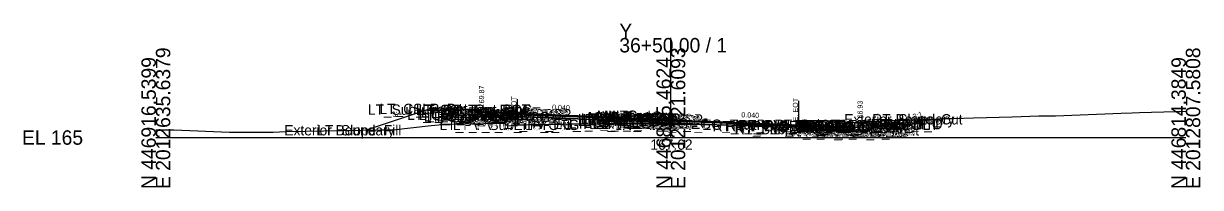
# Model space of a CAD drawing. Extents: x -26 to 3203, y -10 to 9532.
# Drawn here: x 2974.3 to 3202.8, y 490.3 to 522.1 of the extents above; entities that cross this region are included whole.
import ezdxf

# ---------------------------------------------------------------- set-up
doc = ezdxf.new("R2010")
doc.units = 0
for name, color, linetype in [('Default', 7, 'Continuous'), ('Exist CMT Pavement', 7, 'Continuous'), ('Exist Cross Section Cell', 7, 'Continuous'), ('Exist XS Center Line Elevation Label', 7, 'Continuous'), ('Exist XS Ground Line', 7, 'Continuous'), ('Prop CMT Conc Surface', 7, 'Continuous'), ('Prop CMT Concrete Structures', 7, 'Continuous'), ('Prop CMT Pvmt Course 1', 7, 'Continuous'), ('Prop CMT Pvmt Course 1 CG', 7, 'Continuous'), ('Prop CMT Pvmt Course 1 Wedge', 7, 'Continuous'), ('Prop CMT Pvmt Course 2', 7, 'Continuous'), ('Prop CMT Pvmt Course 2 Wedge', 7, 'Continuous'), ('Prop CMT Pvmt Course 3', 7, 'Continuous'), ('Prop CMT Pvmt Course 3 Wedge', 7, 'Continuous'), ('Prop CMT Pvmt Surface', 7, 'Continuous'), ('Prop CMT Pvmt Wedge Surface 1', 7, 'Continuous'), ('Prop CMT Pvmt Wedge Surface 2', 7, 'Continuous'), ('Prop CMT Pvmt Wedge Surface 3', 7, 'Continuous'), ('Prop CMT Slope Grass', 7, 'Continuous'), ('Prop CMT Subgrade Earthwork', 7, 'Continuous'), ('Prop XS Hydro Elevations', 7, 'Continuous'), ('Prop XS Label Text', 7, 'Continuous'), ('Prop XS SE Text', 7, 'Continuous'), ('Prop XS Side Slope Text', 7, 'Continuous'), ('Scratch_Level_0', 7, 'Continuous')]:
    doc.layers.add(name, color=color, linetype=linetype)

msp = doc.modelspace()

# ---------------------------------------------------------------- linework, layer by layer
at = {"layer": 'Exist CMT Pavement'}
msp.add_lwpolyline([(3070.13, 502.45), (3070.68, 502.46), (3071.43, 502.47), (3073.24, 502.5), (3074.4, 502.53), (3074.77, 502.53), (3076.32, 502.56), (3076.88, 502.57), (3077.22, 502.57), (3078.71, 502.6), (3080.14, 502.63), (3081.2, 502.64), (3083.01, 502.66), (3085, 502.68), (3085.38, 502.68), (3086.08, 502.69), (3088.82, 502.72), (3089.84, 502.72), (3091.31, 502.73), (3091.74, 502.73), (3093.28, 502.72), (3094.64, 502.7), (3095.09, 502.7), (3095.86, 502.68), (3096.94, 502.67), (3097.58, 502.66), (3100.05, 502.62), (3100.77, 502.6), (3101.8, 502.59), (3103.4, 502.56), (3105.7, 502.53), (3106.31, 502.53), (3107.91, 502.5), (3109.21, 502.49), (3110.03, 502.48), (3111.1, 502.47), (3111.53, 502.47), (3112.11, 502.47), (3113.36, 502.46), (3115, 502.45), (3115.47, 502.44), (3116.99, 502.43), (3117.9, 502.42), (3118.81, 502.41), (3120.34, 502.4), (3121.06, 502.37), (3123.23, 502.22), (3123.69, 502.18), (3124.79, 502.12)], dxfattribs=at)
at = {"layer": 'Exist Cross Section Cell'}
for p, q in [((3100, 500), (3100, 519.32)), ((3000, 500), (3100, 500)), ((3100, 500), (3200, 500))]:
    msp.add_line(p, q, dxfattribs=at)
at = {"layer": 'Exist XS Ground Line'}
msp.add_lwpolyline([(3000, 501.52), (3000.37, 501.52), (3003.48, 501.48), (3014.31, 501.01), (3022.78, 501.07), (3025.26, 501.14), (3043.64, 501.46), (3046.03, 501.52), (3053.47, 502.34), (3056.38, 502.58), (3063.7, 502.71), (3067.62, 502.76), (3068.42, 502.3), (3070.13, 502.45), (3070.68, 502.46), (3071.43, 502.47), (3073.24, 502.5), (3074.4, 502.53), (3074.77, 502.53), (3076.32, 502.56), (3076.88, 502.57), (3077.22, 502.57), (3078.71, 502.6), (3080.14, 502.63), (3081.2, 502.64), (3083.01, 502.66), (3085, 502.68), (3085.38, 502.68), (3086.08, 502.69), (3088.82, 502.72), (3089.84, 502.72), (3091.31, 502.73), (3091.74, 502.73), (3093.28, 502.72), (3094.64, 502.7), (3095.09, 502.7), (3095.86, 502.68), (3096.94, 502.67), (3097.58, 502.66), (3100.05, 502.62), (3100.77, 502.6), (3101.8, 502.59), (3103.4, 502.56), (3105.7, 502.53), (3106.31, 502.53), (3107.91, 502.5), (3109.21, 502.49), (3110.03, 502.48), (3111.1, 502.47), (3111.53, 502.47), (3112.11, 502.47), (3113.36, 502.46), (3115, 502.45), (3115.47, 502.44), (3116.99, 502.43), (3117.9, 502.42), (3118.81, 502.41), (3120.34, 502.4), (3121.06, 502.37), (3123.23, 502.22), (3123.69, 502.18), (3124.79, 502.12), (3125.27, 502.1), (3125.91, 502.08), (3126.45, 502.32), (3126.79, 502.5), (3127.11, 502.68), (3127.46, 502.77), (3128.1, 502.84), (3129.65, 503.06), (3130.84, 503.2), (3131.19, 503.21), (3133.13, 503.39), (3133.59, 503.09), (3133.9, 502.88), (3134.08, 502.83), (3135.32, 502.91), (3136.4, 503.07), (3137.39, 503.08), (3150.31, 503.57), (3152.8, 503.66), (3154.94, 503.72), (3158.75, 503.83), (3166.29, 504.04), (3171.44, 504.18), (3174.71, 504.24), (3187.42, 504.7), (3189.56, 504.78), (3191.02, 504.84), (3198.06, 505.05), (3198.92, 505.07), (3200, 505.12)], dxfattribs=at)
at = {"layer": 'Prop CMT Conc Surface'}
for points in [[(3058.75, 505.46), (3053.75, 505.56)], [(3063.25, 504.87), (3063.25, 505.37), (3062.75, 505.37)], [(3065.25, 504.87), (3063.25, 504.87)], [(3134.75, 502.09), (3136.75, 501.93)], [(3136.75, 501.93), (3136.75, 502.43), (3137.25, 502.43)], [(3141.25, 502.52), (3146.25, 502.62)]]:
    msp.add_lwpolyline(points, dxfattribs=at)
at = {"layer": 'Prop CMT Concrete Structures'}
for points in [[(3053.75, 505.23), (3053.75, 505.56)], [(3053.75, 505.56), (3058.75, 505.46)], [(3058.75, 505.13), (3053.75, 505.23)], [(3058.75, 505.46), (3058.75, 505.13)], [(3065.25, 504.87), (3063.25, 504.87), (3063.25, 505.37), (3062.75, 505.37)], [(3062.75, 505.37), (3062.75, 504.39), (3065.25, 504.29)], [(3065.25, 504.29), (3065.25, 504.87)], [(3096, 503.64), (3095.99, 503.81), (3095.24, 504.06), (3094, 504.24), (3092.76, 504.22), (3092.01, 503.97), (3092, 503.8)], [(3092, 503.8), (3096, 503.64)], [(3134.75, 502.09), (3136.75, 501.93), (3136.75, 502.43), (3137.25, 502.43)], [(3137.25, 502.43), (3137.25, 501.41), (3134.75, 501.51)], [(3134.75, 501.51), (3134.75, 502.09)], [(3146.25, 502.62), (3141.25, 502.52)], [(3141.25, 502.52), (3141.25, 502.19)], [(3141.25, 502.19), (3146.25, 502.29)], [(3146.25, 502.29), (3146.25, 502.62)]]:
    msp.add_lwpolyline(points, dxfattribs=at)
at = {"layer": 'Prop CMT Pvmt Course 1'}
for points in [[(3092, 503.8), (3065.25, 504.87)], [(3065.25, 504.87), (3065.25, 504.62)], [(3065.25, 504.62), (3070.13, 504.43)], [(3070.13, 504.43), (3070.13, 504.55)], [(3074.77, 504.37), (3092, 503.68)], [(3092, 503.8), (3096, 503.64)], [(3092, 503.55), (3092, 503.8)], [(3092, 503.55), (3092, 503.8)], [(3092, 503.68), (3092, 503.55), (3092, 503.55)], [(3096, 503.39), (3092, 503.55)], [(3096, 503.64), (3096, 503.39)], [(3096, 503.64), (3134.75, 502.09)], [(3096, 503.39), (3096, 503.64)], [(3111.1, 502.91), (3096, 503.52)], [(3096, 503.52), (3096, 503.39), (3096, 503.39)], [(3134.75, 501.84), (3111.1, 502.79)], [(3124.79, 502.24), (3124.79, 502.36)], [(3134.75, 502.09), (3134.75, 501.84)]]:
    msp.add_lwpolyline(points, dxfattribs=at)
at = {"layer": 'Prop CMT Pvmt Course 1 CG'}
for points in [[(3065.25, 504.29), (3062.25, 504.41), (3061.93, 504.09)], [(3061.93, 504.09), (3065.25, 503.95)], [(3065.25, 503.95), (3065.25, 504.29)], [(3134.75, 501.51), (3137.75, 501.39), (3138.1, 501.04)], [(3134.75, 501.17), (3134.75, 501.51)], [(3138.1, 501.04), (3134.75, 501.17)]]:
    msp.add_lwpolyline(points, dxfattribs=at)
at = {"layer": 'Prop CMT Pvmt Course 1 Wedge'}
for points in [[(3092, 503.68), (3070.13, 504.55)], [(3096, 503.52), (3111.1, 502.91)]]:
    msp.add_lwpolyline(points, dxfattribs=at)
at = {"layer": 'Prop CMT Pvmt Course 2'}
for points in [[(3070.13, 504.43), (3065.25, 504.62)], [(3065.25, 504.62), (3065.25, 504.29)], [(3065.25, 504.29), (3070.13, 504.09)], [(3070.13, 504.09), (3070.13, 504.43)], [(3092, 503.55), (3096, 503.39)], [(3092, 503.22), (3092, 503.55)], [(3096, 503.06), (3092, 503.22)], [(3096, 503.39), (3096, 503.06)], [(3124.79, 501.91), (3124.79, 502.24)], [(3124.79, 502.24), (3134.75, 501.84)], [(3134.75, 501.51), (3124.79, 501.91)], [(3134.75, 501.84), (3134.75, 501.51)]]:
    msp.add_lwpolyline(points, dxfattribs=at)
at = {"layer": 'Prop CMT Pvmt Course 2 Wedge'}
for points in [[(3092, 503.55), (3070.13, 504.43)], [(3096, 503.39), (3111.1, 502.79)]]:
    msp.add_lwpolyline(points, dxfattribs=at)
at = {"layer": 'Prop CMT Pvmt Course 3'}
for points in [[(3070.13, 504.09), (3065.25, 504.29)], [(3065.25, 504.29), (3065.25, 503.95)], [(3065.25, 503.95), (3070.13, 503.76)], [(3070.13, 503.76), (3070.13, 504.09)], [(3092, 503.22), (3096, 503.06)], [(3111.1, 502.45), (3124.79, 501.91)], [(3124.79, 501.57), (3124.79, 501.91)], [(3134.75, 501.17), (3124.79, 501.57)], [(3134.75, 501.51), (3134.75, 501.17)]]:
    msp.add_lwpolyline(points, dxfattribs=at)
at = {"layer": 'Prop CMT Pvmt Course 3 Wedge'}
for points in [[(3092, 503.22), (3074.77, 503.91)], [(3096, 503.06), (3110.44, 502.48)]]:
    msp.add_lwpolyline(points, dxfattribs=at)
at = {"layer": 'Prop CMT Pvmt Surface'}
for points in [[(3092, 503.8), (3065.25, 504.87)], [(3092, 503.8), (3096, 503.64)], [(3096, 503.64), (3134.75, 502.09)]]:
    msp.add_lwpolyline(points, dxfattribs=at)
at = {"layer": 'Prop CMT Pvmt Wedge Surface 1'}
for points in [[(3065.25, 504.62), (3065.25, 504.87)], [(3074.77, 504.24), (3065.25, 504.62)], [(3070.13, 504.55), (3070.13, 504.43)], [(3092, 503.68), (3074.77, 504.37)], [(3092, 503.8), (3092, 503.55), (3092, 503.55), (3092, 503.68)], [(3096, 503.64), (3096, 503.39), (3096, 503.39), (3096, 503.52)], [(3096, 503.52), (3111.1, 502.91)], [(3111.1, 502.79), (3124.79, 502.24)], [(3124.79, 502.36), (3124.79, 502.24)], [(3134.75, 501.84), (3134.75, 502.09)]]:
    msp.add_lwpolyline(points, dxfattribs=at)
at = {"layer": 'Prop CMT Pvmt Wedge Surface 2'}
for points in [[(3065.25, 504.62), (3065.25, 504.87)], [(3092, 503.55), (3065.25, 504.62)], [(3092, 503.8), (3092, 503.55)], [(3096, 503.64), (3096, 503.39)], [(3096, 503.39), (3124.79, 502.24)], [(3134.75, 501.84), (3134.75, 502.09)]]:
    msp.add_lwpolyline(points, dxfattribs=at)
at = {"layer": 'Prop CMT Pvmt Wedge Surface 3'}
for p, q in [((3070.13, 504.09), (3092, 503.22)), ((3096, 503.06), (3124.79, 501.91))]:
    msp.add_line(p, q, dxfattribs=at)
for points in [[(3065.25, 504.29), (3065.25, 504.87)], [(3092, 503.22), (3065.25, 504.29)], [(3092, 503.8), (3092, 503.22)], [(3096, 503.64), (3096, 503.06)], [(3096, 503.06), (3134.75, 501.51)], [(3134.75, 501.51), (3134.75, 502.09)]]:
    msp.add_lwpolyline(points, dxfattribs=at)
at = {"layer": 'Prop CMT Slope Grass'}
for points in [[(3062.75, 505.37), (3053.25, 505.56), (3040.81, 501.41)], [(3146.25, 502.61), (3146.75, 502.62), (3149.52, 503.54)], [(3137.25, 502.43), (3146.25, 502.61)]]:
    msp.add_lwpolyline(points, dxfattribs=at)
at = {"layer": 'Prop CMT Subgrade Earthwork'}
msp.add_line((3070.13, 503.76), (3070.13, 502.45), dxfattribs=at)
for points in [[(3065.25, 503.95), (3061.93, 504.09), (3060.6, 505.41)], [(3070.13, 503.76), (3065.25, 503.95)], [(3124.79, 501.57), (3124.79, 502.12)], [(3124.79, 501.57), (3134.75, 501.17)], [(3134.75, 501.17), (3138.1, 501.04), (3139.53, 502.48)]]:
    msp.add_lwpolyline(points, dxfattribs=at)
at = {"layer": 'Prop XS Label Text'}
for p, q in [((3070.13, 507.45), (3070.13, 502.45)), ((3124.79, 507.12), (3124.79, 502.12))]:
    msp.add_line(p, q, dxfattribs=at)

# ---------------------------------------------------------------- texts
at = {"layer": 'Default'}
msp.add_text('-', height=0.0001, dxfattribs=at).set_placement((3000, 500))
at = {"layer": 'Exist Cross Section Cell'}
for s, p in [('Y', (3090, 519.32)), ('36+50.00 / 1', (3090, 516.52)), ('EL 165', (2974, 498.6))]:
    msp.add_text(s, height=2.8, dxfattribs=at).set_placement(p)
for s, p in [('E 2012635.6379', (3002.8, 490)), ('E 2012721.6093', (3102.8, 490)), ('E 2012807.5808', (3202.8, 490)), ('N 446916.5399', (3000, 490)), ('N 446865.4624', (3100, 490)), ('N 446814.3849', (3200, 490))]:
    msp.add_text(s, height=2.8, rotation=90, dxfattribs=at).set_placement(p)
at = {"layer": 'Exist XS Center Line Elevation Label'}
msp.add_text('167.62', height=2, dxfattribs=at).set_placement((3096.03, 497.62))
at = {"layer": 'Prop XS Hydro Elevations'}
for s, p in [('169.87', (3063.75, 505.87)), ('166.93', (3137.25, 502.93))]:
    msp.add_text(s, height=1, rotation=90, dxfattribs=at).set_placement(p)
at = {"layer": 'Prop XS Label Text'}
for p in [(3070.03, 503.47), (3124.69, 503.15)]:
    msp.add_text('E. EOT', height=1, rotation=90, dxfattribs=at).set_placement(p)
at = {"layer": 'Prop XS SE Text'}
for p in [(3076.92, 505.41), (3113.67, 503.94)]:
    msp.add_text('0.040', height=1, rotation=357.7094, dxfattribs=at).set_placement(p)
at = {"layer": 'Prop XS Side Slope Text'}
for p in [(3046.04, 503.95), (3147.15, 503.54)]:
    msp.add_text('3:1', height=1, rotation=18.4349, dxfattribs=at).set_placement(p)
at = {"layer": 'Scratch_Level_0'}
for s, p in [('LT_Sub_Trench_Out_DLT', (3041.17, 504.41)), ('LT_CSLP_Pnt', (3043.42, 504.56)), ('LT_CG1_Shelf_Out', (3048.8, 503.41)), ('LT_CG_Top_Face', (3050.51, 504.37)), ('LT_CG_Top_BOC', (3051.03, 504.37)), ('LT_CG_Bot_BOC', (3051.06, 503.39)), ('LT_CG_Top_Gut', (3051.49, 503.87)), ('LT_Sub_OEOP', (3052.04, 503.09)), ('LT_Sub_OEOT_CG', (3052.62, 502.95)), ('LT_CG_Bot_IE', (3055.16, 503.29)), ('LT_Sub_OEOT', (3055.33, 502.95)), ('LT_PV2_OEOT', (3055.42, 503.62)), ('LT_PV3_OEOT', (3055.42, 503.29)), ('LT_PV1_OEOT', (3055.99, 503.87)), ('LT_PV2_OEEOP', (3059.45, 503.43)), ('LT_PV3_OEEOP', (3059.45, 503.09)), ('LT_PV1_OEEOP', (3060.01, 503.55)), ('MI_Top In', (3085.61, 503.22)), ('MI_Top Out', (3086.47, 503.06)), ('MI_Crown', (3087.07, 503.24)), ('LT_PV_Sub_Tie_Out', (3055.1, 501.45)), ('LT_PV_OEEOP_EG', (3057.68, 501.45)), ('LT_Sub_OEEOP', (3059.35, 502.76)), ('LT_PV_EG_TestPt', (3067.48, 501.64)), ('LT_PV_IEEOP_EG', (3080.19, 501.73)), ('LT_PV2_IEEOP', (3081.95, 502.55)), ('LT_PV3_IEEOP', (3081.95, 502.22)), ('LT_PV1_IEEOP', (3082.52, 502.68)), ('LT_PV2_PGL1', (3082.88, 502.55)), ('LT_PV3_PGL1', (3082.88, 502.22)), ('LT_PV2_PGL', (3083.21, 502.55)), ('LT_PV3_PGL', (3083.21, 502.22)), ('LT_PV4_PGL', (3083.21, 501.88)), ('LT_PV1_PGL', (3083.78, 502.8)), ('MI_Face In', (3083.9, 502.97)), ('RT_PV_IEEOP_EG', (3084.14, 501.68)), ('RT_PV2_IEEOP', (3085.91, 502.39)), ('RT_PV3_IEEOP', (3085.91, 502.06)), ('MI_Face Out', (3086.26, 502.81)), ('RT_PV1_IEEOP', (3086.47, 502.52)), ('RT_PV2_PGL1', (3086.83, 502.39)), ('RT_PV3_PGL1', (3086.83, 502.06)), ('RT_PV2_PGL', (3087.17, 502.39)), ('RT_PV3_PGL', (3087.17, 502.06)), ('RT_PV4_PGL', (3087.17, 501.72)), ('MI_Bot Out', (3087.26, 502.64)), ('RT_PV1_PGL', (3087.73, 502.64)), ('RT_PV_EG_TestPt', (3095.98, 501.49)), ('RT_PV_Sub_Tie_Out', (3108.11, 501.22)), ('RT_PV_OEEOP_EG', (3110.72, 501.22)), ('RT_PV2_OEEOP', (3112.49, 501.3)), ('RT_PV3_OEEOP', (3112.49, 500.97)), ('RT_PV1_OEEOP', (3113.05, 501.43)), ('RT_Sub_Trench_Out_DLT', (3120.05, 501.48)), ('RT_CG_Top_Face', (3123.96, 501.43)), ('RT_PV2_OEOT', (3124.88, 500.84)), ('RT_CG_Top_Gut', (3124.94, 500.93)), ('RT_PV1_OEOT', (3125.44, 501.09)), ('RT_CG_Top_BOC', (3125.49, 501.43)), ('Exterior Boundary', (3133.66, 502.54)), ('RT_Shld_O', (3138.79, 501.61)), ('RT_Slope_Cut', (3139.11, 502.54)), ('CSLP_Pnt', (3139.62, 501.62)), ('Exterior Boundary', (3024.95, 500.41)), ('LT_Slope_Fill', (3031.33, 500.41)), ('RT_Sub_OEEOP', (3112.39, 500.64)), ('RT_Sub_OEOT_CG', (3122.07, 500.17)), ('RT_CG1_Shelf_Out', (3124.25, 500.39)), ('RT_CG_Bot_IE', (3124.62, 500.51)), ('RT_Sub_OEOT', (3124.78, 500.17)), ('RT_PV3_OEOT', (3124.88, 500.51)), ('RT_CG_Bot_BOC', (3125.52, 500.41)), ('RT_Sub_OEOP', (3128.16, 500.04))]:
    msp.add_text(s, height=2, dxfattribs=at).set_placement(p)

doc.saveas('drawing.dxf')
